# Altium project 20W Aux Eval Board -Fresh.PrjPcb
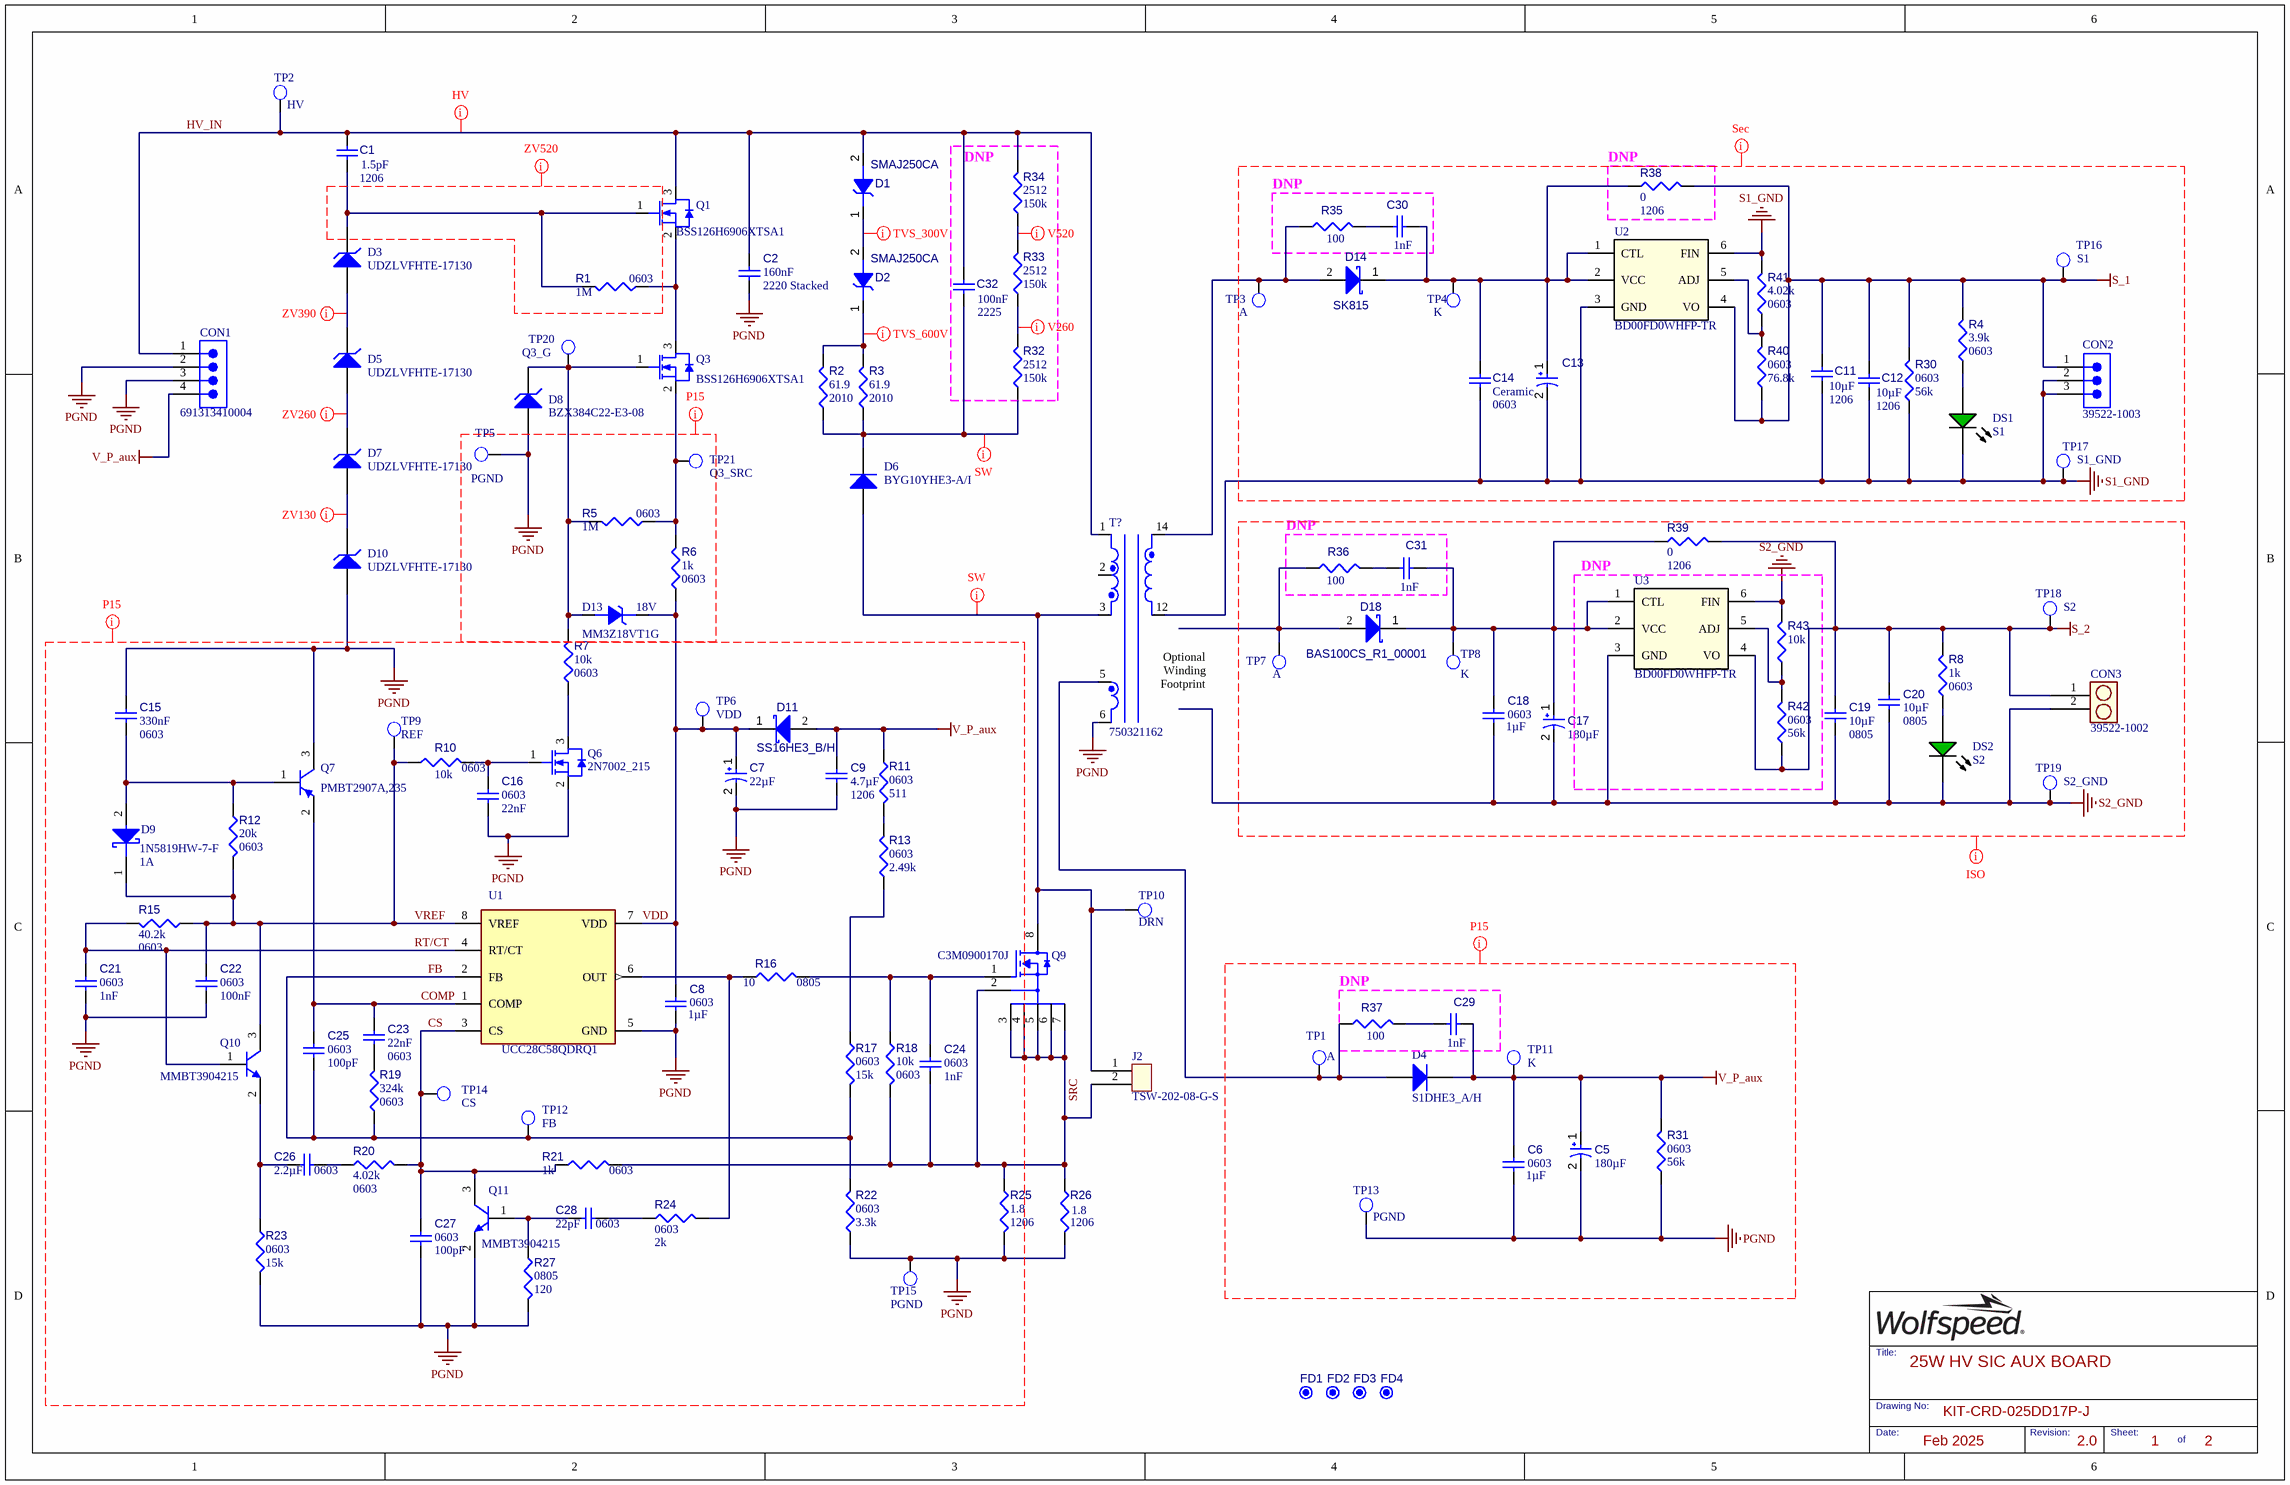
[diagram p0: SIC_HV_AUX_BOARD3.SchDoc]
Date: Feb 2025; DocumentNumber: KIT-CRD-025DD17P-J; Revision: 2.0; Title: 25W HV SIC AUX BOARD
2 sheets, 135 parts. Net scope: global (net labels, ports and power ports of the same name join across sheets).
Board file: HV_SIC_AUX_BOARD.PcbDoc
Sheets:
  SIC_HV_AUX_BOARD3.SchDoc
  Mechanicals.SchDoc

## Sheet SIC_HV_AUX_BOARD3.SchDoc: 25W HV SIC AUX BOARD
size 431 x 279 mm; SheetNumber: 1; SheetTotal: 2

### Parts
C1  value 1.5pF  Case/Package: 1206  [CAPC3316X19N]  (hidden comment: 1206Y1K01P50DAR)
C2  value 160nF  Case/Package: 2220 Stacked  [WS_C2220_B_Stacked]  (hidden comment: C2220C164KFRLCTU)
C5  value 180µF  [870235574001-Footprint-1]  (hidden comment: 870235574001)
C6  value 1µF  Case/Package: 0603  [FP-C0603C-CF-IPC_B]  (hidden comment: C1608X7R1V105K080AE)
C7  value 22µF  [875575659001-Footprint-1]  (hidden comment: 875575659001)
C8  value 1µF  Case/Package: 0603  [FP-C0603C-CF-IPC_B]  (hidden comment: C1608X7R1V105K080AE)
C9  value 4.7µF  Case/Package: 1206  [CAPC3316X19N]  (hidden comment: UMK316AB7475KL-T)
C11  value 10µF  Case/Package: 1206  [CAPC3316X19N]  (hidden comment: CL31B106KAHNFNE)
C12  value 10µF  Case/Package: 1206  [CAPC3316X19N]  (hidden comment: CL31B106KAHNFNE)
C13  EEE-FP1V221AP  [FP-FPF-MFG]  (value not drawn)
C14  Capacitor Type: Ceramic  Case/Package: 0603  [FP-C0603C-CF-IPC_B]  (hidden comment: 06035C105KAT2A)
C15  value 330nF  Case/Package: 0603  [WFP_C0603_C]  (hidden comment: CC0603KRX7R8BB334)
C16  value 22nF  Case/Package: 0603  [FP-C0603C-CF-IPC_B]  (hidden comment: CGA3E2X7R1H223K080AA)
C17  value 180µF  [WCAP-PT5H_D6.3H11]  (hidden comment: 870235373002)
C18  value 1µF  Case/Package: 0603  [FP-C0603C-CF-IPC_B]  (hidden comment: C1608X7R1V105K080AE)
C19  value 10µF  Case/Package: 0805  [CAPC2012X15N]  (hidden comment: CC0805MKX7R7BB106)
C20  value 10µF  Case/Package: 0805  [CAPC2012X15N]  (hidden comment: CC0805MKX7R7BB106)
C21  value 1nF  Case/Package: 0603  [FP-C0603C-CF-IPC_B]  (hidden comment: GRM1885C1H102GA01D)
C22  value 100nF  Case/Package: 0603  [FP-C0603C-CF-IPC_B]  (hidden comment: C0603C104K5RAC7411)
C23  value 22nF  Case/Package: 0603  [FP-C0603C-CF-IPC_B]  (hidden comment: CGA3E2X7R1H223K080AA)
C24  value 1nF  Case/Package: 0603  [FP-C0603C-CF-IPC_B]  (hidden comment: GRM1885C1H102GA01D)
C25  value 100pF  Case/Package: 0603  [FP-C0603C-CF-IPC_B]  (hidden comment: CC0603KRX7R9BB101)
C26  value 2.2µF  Case/Package: 0603  [FP-C0603C-CF-IPC_B]  (hidden comment: GMC10X7R225K16NT)
C27  value 100pF  Case/Package: 0603  [FP-C0603C-CF-IPC_B]  (hidden comment: CC0603KRX7R9BB101)
C28  value 22pF  Case/Package: 0603  [FP-C0603C-CF-IPC_B]  (hidden comment: C0603C220K5GACTU)
C29  value 1nF  [CAPC3316X19N]  (hidden comment: GRM31B5C2J102JW01L)
C30  value 1nF  [CAPC3316X19N]  (hidden comment: GRM31B5C2J102JW01L)
C31  value 1nF  [CAPC3316X19N]  (hidden comment: GRM31B5C2J102JW01L)
C32  value 100nF  Case/Package: 2225  [CAPC2225(5664)150_N]  (hidden comment: C2225C104KFRACTU)
CON1  691313410004  [691313410004]
CON2  39522-1003  [39522-1002-Footprint-1]
CON3  39522-1002  [39522-1002-Footprint-1]
D1  SMAJ250CA  [DO-214AC_SMA_B]
D2  SMAJ250CA  [DO-214AC_SMA_B]
D3  UDZLVFHTE-17130  [WS-SOD323F_B]
D4  S1DHE3_A/H  [DO-214AC_SMA_B]
D5  UDZLVFHTE-17130  [WS-SOD323F_B]
D6  BYG10YHE3-A/I  [DO-214AC_SMA_B]
D7  UDZLVFHTE-17130  [WS-SOD323F_B]
D8  BZX384C22-E3-08  [DIOD-SOD323-2-A_V]
D9  1N5819HW-7-F  Forward Current: 1A  [WS_SOD123_B]
D10  UDZLVFHTE-17130  [WS-SOD323F_B]
D11  SS16HE3_B/H  [DO-214AC_SMA_B]
D13  MM3Z18VT1G  Voltage Rating (DC): 18V  [DIOD-SOD323-2-A_V]
D14  SK815  [DO-214AB (SMC) MD]
D18  BAS100CS_R1_00001  [WS-SOD323F_B]
DS1  S1  [WL-SMCW_0603_150060xx75000]
DS2  S2  [WL-SMCW_0603_150060xx75000]
FD1  FID1X2R Two Sided  [FID1X2R Two Sided-Footprint-1]  (value not drawn)  (no BOM)
FD2  FID1X2R Two Sided  [FID1X2R Two Sided-Footprint-1]  (value not drawn)  (no BOM)
FD3  FID1X2R Two Sided  [FID1X2R Two Sided-Footprint-1]  (value not drawn)  (no BOM)
FD4  FID1X2R Two Sided  [FID1X2R Two Sided-Footprint-1]  (value not drawn)  (no BOM)
J2  TSW-202-08-G-S  [TSW-202-24-T-S-Footprint-2]
Q1  BSS126H6906XTSA1  [WFP_SOT23-3_IPC_B]
Q3  BSS126H6906XTSA1  [WFP_SOT23-3_IPC_B]
Q6  2N7002_215  [WFP_SOT23-3_IPC_B]
Q7  PMBT2907A,235  [WFP_SOT23-3_IPC_B]
Q9  C3M0900170J  [TO-263-7XL_CRW]
Q10  MMBT3904215  [NXP-SOT23_N]
Q11  MMBT3904215  [NXP-SOT23_N]
R1  value 1M  Case/Package: 0603  [FP-AC0603-IPC_B]  (hidden comment: RMCF0603FT1M00)
R2  value 61.9  Case/Package: 2010  [R2010_MD]  (hidden comment: CRCW201061R9FKEFHP)
R3  value 61.9  Case/Package: 2010  [R2010_MD]  (hidden comment: CRCW201061R9FKEFHP)
R4  value 3.9k  Case/Package: 0603  [FP-AC0603-IPC_B]  (hidden comment: RMCF0603FT3K90)
R5  value 1M  Case/Package: 0603  [FP-AC0603-IPC_B]  (hidden comment: RMCF0603FT1M00)
R6  value 1k  Case/Package: 0603  [FP-AC0603-IPC_B]  (hidden comment: RMCF0603FG1K00)
R7  value 10k  Case/Package: 0603  [FP-AC0603-IPC_B]  (hidden comment: RG1608P-103-B-T5)
R8  value 1k  Case/Package: 0603  [FP-AC0603-IPC_B]  (hidden comment: RMCF0603FG1K00)
R10  value 10k  Case/Package: 0603  [FP-AC0603-IPC_B]  (hidden comment: RG1608P-103-B-T5)
R11  value 511  Case/Package: 0603  [WFP_R0603_B]  (hidden comment: RC0603FR-07511RL)
R12  value 20k  Case/Package: 0603  [FP-AC0603-IPC_B]  (hidden comment: RMCF0603FT20K0)
R13  value 2.49k  Case/Package: 0603  [FP-AC0603-IPC_B]  (hidden comment: Copy of ERJ-3EKF2701V)
R15  value 40.2k  Case/Package: 0603  [FP-AC0603-IPC_B]  (hidden comment: AC0603FR-0740K2L)
R16  value 10  Case/Package: 0805  [RESC2012X05M]  (hidden comment: RC0805FR-1310RL)
R17  value 15k  Case/Package: 0603  [FP-AC0603-IPC_B]  (hidden comment: RT0603BRE0715KL)
R18  value 10k  Case/Package: 0603  [FP-AC0603-IPC_B]  (hidden comment: RG1608P-103-B-T5)
R19  value 324k  Case/Package: 0603  [FP-AC0603-IPC_B]  (hidden comment: AC0603FR-07324KL)
R20  value 4.02k  Case/Package: 0603  [FP-AC0603-IPC_B]  (hidden comment: RMCF0603FT4K02)
R21  value 1k  Case/Package: 0603  [FP-AC0603-IPC_B]  (hidden comment: RMCF0603FG1K00)
R22  value 3.3k  Case/Package: 0603  [FP-AC0603-IPC_B]  (hidden comment: RMCF0603FT3K30)
R23  value 15k  Case/Package: 0603  [FP-AC0603-IPC_B]  (hidden comment: RT0603BRE0715KL)
R24  value 2k  Case/Package: 0603  [FP-AC0603-IPC_B]  (hidden comment: ERJ-3EKF2001V)
R25  value 1.8  Case/Package: 1206  [RESC3015X06N]  (hidden comment: CRCW12061R80FKEAHP)
R26  value 1.8  Case/Package: 1206  [RESC3015X06N]  (hidden comment: CRCW12061R80FKEAHP)
R27  value 120  Case/Package: 0805  [FP-CRGP0805-IPC_B]  (hidden comment: CRGP0805F120R)
R30  value 56k  Case/Package: 0603  [FP-AC0603-IPC_B]  (hidden comment: 56k 0603)
R31  value 56k  Case/Package: 0603  [FP-AC0603-IPC_B]  (hidden comment: 56k 0603)
R32  value 150k  Case/Package: 2512  [RESC6332X07N]  (hidden comment: CRCW2512150KFKEG)
R33  value 150k  Case/Package: 2512  [RESC6332X07N]  (hidden comment: CRCW2512150KFKEG)
R34  value 150k  Case/Package: 2512  [RESC6332X07N]  (hidden comment: CRCW2512150KFKEG)
R35  value 100  [RESC3015X06N]  (hidden comment: CRCW1206100RFKEA)
R36  value 100  [RESC3015X06N]  (hidden comment: CRCW1206100RFKEA)
R37  value 100  [RESC3015X06N]  (hidden comment: CRCW1206100RFKEA)
R38  value 0  Case/Package: 1206  [RESC3015X06N]  (hidden comment: RC1206JR-100RL)
R39  value 0  Case/Package: 1206  [RESC3015X06N]  (hidden comment: RC1206JR-100RL)
R40  value 76.8k  Case/Package: 0603  [FP-AC0603-IPC_B]  (hidden comment: RC0603FR-0776K8L)
R41  value 4.02k  Case/Package: 0603  [FP-AC0603-IPC_B]  (hidden comment: RMCF0603FT4K02)
R42  value 56k  Case/Package: 0603  [FP-AC0603-IPC_B]  (hidden comment: 56k 0603)
R43  value 10k  [FP-AC0603-IPC_B]  (hidden comment: Resistor 10k +/-1% 0603 100 mW)
T?  750321162  [750345357-Footprint-1]
TP1  A  [TEST_POINT_SM_REC]
TP2  HV  [TEST_POINT_SM_REC]
TP3  A  [TEST_POINT_SM_REC]
TP4  K  [TEST_POINT_SM_REC]
TP5  PGND  [5012-Footprint-1]
TP6  VDD  [TEST_POINT_SM_REC]
TP7  A  [TEST_POINT_SM_REC]
TP8  K  [TEST_POINT_SM_REC]
TP9  REF  [TEST_POINT_SM_REC]
TP10  DRN  [TEST_POINT_SM_REC]
TP11  K  [TEST_POINT_SM_REC]
TP12  FB  [TEST_POINT_SM_REC]
TP13  PGND  [5012-Footprint-1]
TP14  CS  [TEST_POINT_SM_REC]
TP15  PGND  [5012-Footprint-1]
TP16  S1  [5012-Footprint-1]
TP17  S1_GND  [5012-Footprint-1]
TP18  S2  [5012-Footprint-1]
TP19  S2_GND  [5012-Footprint-1]
TP20  Q3_G  [TEST_POINT_SM_REC]
TP21  Q3_SRC  [TEST_POINT_SM_REC]
U1  UCC28C58QDRQ1  [WFP_SOIC127P6-8_IPC-B]
U2  BD00FD0WHFP-TR  [BD00FD0WHFP-TR-Footprint-1]
U3  BD00FD0WHFP-TR  [BD00FD0WHFP-TR-Footprint-1]

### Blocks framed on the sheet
DNP: C32 R32-R34
DNP: C30 R35
DNP: R38
DNP: C31 R36
DNP: R42 R43 U3
DNP: C29 R37

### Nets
PGND: C2.2 C5.2 C6.2 C7.2 C8.2 C9.2 C15.2 C16.1 C21.1 C22.1 C27.1 CON1.2 CON1.3 D8.2(A) D10.2(A) Q6.2(S) Q7.3(C) Q11.2(E) R22.1 R23.2 R25.2 R26.2 R27.2 R31.1 T?.6(Pri2-) TP5.1(TP) TP13.1(TP) TP15.1(TP) U1.5(GND)
S1_GND: C11.2 C12.2 C13.2 C14.2 CON2.2 CON2.3 DS1.1(K) R30.1 R41.2 T?.12(Sec1-) TP17.1(TP) U2.3(GND) U2.6(FIN)
S2_GND: C17.2 C18.2 C19.1 C20.1 CON3.2 DS2.1(K) R43.2 TP19.1(TP) U3.3(GND) U3.6(FIN)
S_1: C11.1 C12.1 CON2.1 R4.2 R30.2 R38.2 R40.1 TP16.1(TP) U2.4(VO)
S_2: C19.2 C20.2 CON3.1 R8.2 R39.2 R42.1 TP18.1(TP) U3.4(VO)
V_P_aux: C5.1 C6.1 C9.1 C29.1 CON1.4 D4.1(K) D11.2(A) R11.1 R31.2 TP11.1(TP)
COMP: C23.2 C25.2 Q7.2(E) U1.1(COMP)
CS: C27.2 Q11.3(C) R20.2 R21.1 TP14.1(TP) U1.3(CS)
FB: C25.1 R17.2 R19.1 R22.2 TP12.1(TP) U1.2(FB)
HV_IN: C1.1 C2.1 C32.1 CON1.1 D1.2(A) Q1.3(D) R34.1 T?.1(Pri1+) TP2.1(TP)
RT/CT: C21.2 Q10.1(B) R15.2 U1.4(RT/CT)
SRC: C24.1 J2.2 Q9.2(Driver_Source) Q9.3(Power_Source) Q9.4(Power_Source) Q9.5(Power_Source) Q9.6(Power_Source) Q9.7(Power_Source) R18.2 R21.2 R25.1 R26.1
VDD: C7.1 C8.1 D11.1(K) D13.2(CATHODE) R6.1 TP6.1(TP) U1.7(VDD)
VREF: C22.2 D9.1(C) Q10.3(C) R10.1 R12.2 R15.1 TP9.1(TP) U1.8(VREF)
NetC1_2: C1.2 D3.1(K) Q1.1(G) R1.2
NetC13_1: C13.1 C14.1 C30.1 D14.1(K) R38.1 TP4.1(TP) U2.1(CTL) U2.2(VCC)
NetC15_1: C15.1 D9.2(A) Q7.1(B) R12.1
NetC16_2: C16.2 Q6.1(G) R10.2
NetC17_1: C17.1 C18.1 C31.1 D18.1(K) R39.1 TP8.1(TP) U3.1(CTL) U3.2(VCC)
NetC23_1: C23.1 R19.2
NetC24_2: C24.2 Q9.1(Gate) R16.2 R18.1
NetC26_1: C26.1 Q10.2(E) R23.1
NetC26_2: C26.2 R20.1
NetC28_1: C28.1 R24.1
NetC28_2: C28.2 Q11.1(B) R27.1
NetC29_2: C29.2 R37.2
NetC30_2: C30.2 R35.2
NetC31_2: C31.2 R36.2
NetC32_2: C32.2 D6.1(K) R2.1 R3.1 R32.2
NetD1_1: D1.1(A) D2.2(A)
NetD2_1: D2.1(A) R2.2 R3.2
NetD3_2: D3.2(A) D5.1(K)
NetD4_2: D4.2(A) R37.1 T?.5(Pri2+) TP1.1(TP)
NetD5_2: D5.2(A) D7.1(K)
NetD6_2: D6.2(A) J2.1 Q9.8(Drain) T?.3(Pri1-) TP10.1(TP)
NetD7_2: D7.2(A) D10.1(K)
NetD8_1: D8.1(K) D13.1(ANODE) Q3.1(G) R5.2 R7.2 TP20.1(TP)
NetD14_2: D14.2(A) R35.1 T?.14(Sec1+) TP3.1(TP)
NetD18_2: D18.2(A) R36.1 TP7.1(TP)
NetDS1_2: DS1.2(A) R4.1
NetDS2_2: DS2.2(A) R8.1
NetQ1_2: Q1.2(S) Q3.3(D) R1.1
NetQ3_2: Q3.2(S) R5.1 R6.2 TP21.1(TP)
NetQ6_3: Q6.3(D) R7.1
NetR11_2: R11.2 R13.2
NetR13_1: R13.1 R17.1
NetR16_1: R16.1 R24.2 U1.6(OUT)
NetR32_1: R32.1 R33.2
NetR33_1: R33.1 R34.2
NetR40_2: R40.2 R41.1 U2.5(ADJ)
NetR42_2: R42.2 R43.1 U3.5(ADJ)

Not connected (* = marked no-connect by the designer): T? 2(Pri1+)

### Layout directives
net class Sec: S1_GND, S_1
net class ISO: S2_GND, S_2
net class P15: COMP, CS, FB, PGND, RT/CT, V_P_aux, VDD, VREF
net class HV: HV_IN
net class ZV130: NetD7_2
net class ZV260: NetD5_2
net class ZV390: NetD3_2
net class SW: NetC32_2, NetD6_2
net class V260: NetR32_1
net class ZV520: (no net found under the mark)
net class V520: NetR33_1
net class TVS_300V: NetD1_1
net class TVS_600V: NetD2_1

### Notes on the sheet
- (near T?) Optional Winding Footprint

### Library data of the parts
C1 = CMP-001-00194-6: MLCC, 1206, Y5V, 1uf, .10%, 0.50Vdc, Palliadum Silver; Capacitor Type: Ceramic; Temperature Coefficient: COG/NPO; Tolerance: 33%; Voltage Rating: 1kV
C2 = CMP-001-00220-1: 0.16 µF ±10% 1500V (1.5kV) Ceramic Capacitor X7R 2220
C5 = CMP-001-00223-1: WCAP-PT5H Aluminum Polymer Capacitors, 180uF, 16VDC, +/-20%; Capacitor Type: Electrolytic; Tolerance: 20%; Voltage Rating: 16V
C6 C8 C18 = CMP-001-00097-20: Ceramic Capacitor, Multilayer, Ceramic, 35V, 10% +Tol, 10% -Tol, X7R, 15% TC, 1uF, Surface Mount, 0603
C7 = CMP-001-00222-1: WCAP-ASLL Aluminum Hybrid Electrolytic Capacitor, 22uF, 35VDC, +/-20%; Tolerance: 20%; Voltage Rating: 35V
C9 = CMP-001-00161-7: Ceramic Capacitor, Multilayer, Ceramic, 4.7 µF ±10% 50V Ceramic Capacitor X7R 1206
C11 C12 = CMP-001-00158-8: Cap Ceramic 10uF 25V X7R 10% SMD 1206 125°C Embossed T/R
C13 = CMP-001-00219-2: Aluminum Electrolytic Capacitor, Polarized, Aluminum (wet), 35V, 20% +Tol, 20% -Tol, 220uF, Surface Mount, 3333; Capacitor Type: Aluminium; Value: 220µF
C14 = CMP-001-00122-18: Ceramic Capacitor, Multilayer, Ceramic, 50V, 10% +Tol, 10% -Tol, X7R, 15% TC, 1uF, Surface Mount, 0603; Value: 1µF
C15 = CMP-001-00201-6: Ceramic Capacitor, Multilayer, Ceramic, 25V, 10% +Tol, 10% -Tol, X7R, 15% TC, 0.33uF, Surface Mount, 0603
C16 C23 = CMP-001-00120-19: Ceramic Capacitor, Multilayer, Ceramic, 50V, 10% +Tol, 10% -Tol, X7R, 15% TC, 0.022uF, Surface Mount, 0603
C17 = CMP-001-00221-1: CAP ALUM POLY 180UF 20% 16V TH; Capacitor Type: Aluminium
C19 C20 = CMP-001-00199-5: Ceramic Capacitor, Multilayer, Ceramic, 16V, 20% +Tol, 20% -Tol, X7R, 15% TC, 10uF, Surface Mount, 0805
C21 C24 = CMP-001-00098-21: Ceramic Capacitor, Multilayer, Ceramic, 50V, 2% +Tol, 2% -Tol, C0G, -/+30ppm/Cel TC, 0.001uF, Surface Mount, 0603
C22 = CMP-001-00086-20: Ceramic Capacitor, Multilayer, Ceramic, 50V, 10% +Tol, 10% -Tol, X7R, 15% TC, 0.1uF, Surface Mount, 0603
C25 C27 = CMP-001-00096-18: Ceramic Capacitor, Multilayer, Ceramic, 50V, 10% +Tol, 10% -Tol, X7R, 15% TC, 0.0001uF, Surface Mount, 0603
C26 = CMP-001-00123-18: Ceramic Capacitor, Multilayer, Ceramic, 16V, 10% +Tol, 10% -Tol, X7R, 15% TC, 2.2uF, Surface Mount, 0603
C28 = CMP-001-00112-18: Ceramic Capacitor, Multilayer, Ceramic, 50V, 1% +Tol, 1% -Tol, C0G, 30ppm/Cel TC, 0.000022uF, Surface Mount, 0603
C29-C31 = CMP-001-00217-1: Ceramic Capacitor, Multilayer, Ceramic, 630V, 5% +Tol, 5% -Tol, C0G, 30ppm/Cel TC, 0.001uF, Surface Mount, 1206; Temperature Coefficient: COG
C32 = CMP-001-00008-7: Cap Ceramic 0.1uF 1500V X7R 10% SMD 2225 125°C Embossed Plastic T/R; Voltage Rating: 1.5kV
CON1 = CMP-002-00276-1: Strip Terminal Block, 20A, 1 Row(s), 1 Deck(s); Connector Type: Shrouded Header; Gender: Male; Rated Voltage: 300V
CON2 = CMP-002-00195-6: Conn Shrouded Header (4 Sides) HDR 3 POS 5mm Solder RA Thru-Hole Eurostyle™; Gender: Male; Connector Type: Terminal Block
CON3 = CMP-002-00120-6: Conn Shrouded Header (4 Sides) HDR 2 POS 5mm Solder RA Thru-Hole Eurostyle™; Connector Type: Terminal Block; Gender: Male
D1 D2 = CMP-004-00090-2: TVS DIODE 250VWM 405VC DO214AC405V Clamp 1A Ipp Tvs Diode Surface Mount DO-214AC
D3 D5 D7 D10 = CMP-004-00084-2: Zener Diode, 130V, 0.2W, Sod-323Fl Rohs Compliant: Yes; Zener Voltage: 130
D4 = CMP-004-00089-3: Rectifier Diode, 1 Phase, 1 Element, 1A, 400V V(RRM), Silicon, DO-214AC; Forward Voltage: 1.1V; Max Surge Current: 40A; Peak Inverse Voltage: 200V
D6 = CMP-004-00085-3: Standard Avalanche Rectifier 1600V 1.5A Automotive 2-Pin DO-214AC T/R; Forward Voltage: 1.15V; Max Surge Current: 30A; Peak Inverse Voltage: 1.6kV
D8 = CMP-004-00086-2: Zener Diode, 22V V(Z), 5%, 0.2W, Silicon, Unidirectional
D9 = CMP-004-00065-4: DIODE SCHOTTKY 40V 1A SOD123; Forward Voltage: 450mV
D11 = CMP-00035-3: Rectifier Diode, Schottky, 1 Phase, 1 Element, 1A, 60V V(RRM), Silicon, DO-214AC; Forward Voltage: 750mV; Max Surge Current: 40A
D13 = CMP-00028-3: Vz=18V 16.8V~19.1V Izt=5mA; Material: Plastic; Tolerance: 6%; Max Power Dissipation: 300mW; Max Reverse Current: 50nA; Power Rating: 200mW; Impedance: 45R; Zener Current: 10mA; Test Current: 5mA; Forward Voltage: 900mV
D14 = CMP-00045-2: Rectifier Diode Schottky 150V 8A 2-Pin SMC T/R; Forward Voltage: 870mV
D18 = CMP-00037-1: OEMs, CMs ONLY (NO BROKERS); Forward Voltage: 850mV; Max Surge Current: 5.5A; Peak Inverse Voltage: 100V
DS1 DS2 = CMP-007-00045-2: Single Color LED, Bright Green, Water Clear, 1.1mm; Forward Voltage: 2V; Max Power Dissipation: 72mW
FD1-FD4 = CMP-00028-00054-3: Fiducial - Round 1x2mm
J2 = CMP-002-00256-2: Board Connector, 2 Contact(s), 1 Row(s), Male, Straight, 0.2 inch Pitch, Solder Terminal, Black Insulator, Receptacle
Q1 Q3 = CMP-013-00102-1: Trans MOSFET N-CH 600V 0.021A Automotive 3-Pin SOT-23 T/R; Vgs (Max): 20V; Transistor Type: NMOS; Power: 500mW
Q6 = CMP-013-00011-7: N-channel Trench MOSFET, 60 V, 300 mA, -65 to 150 degC, 3-Pin SOT-23 (TO-236AB), RoHS, Tape and Reel; Manufacturer: NXP Semiconductors; Input Capacitance: 50pF; Rds On Max: 5Ohm; Vds Max: 60V; Package Version: Feb-16; Nominal Vgs: 2V; Elements: 1; Power: 830mW
Q7 = CMP-013-00100-1: Small Signal Bipolar Transistor, 0.6A I(C), 60V V(BR)CEO, 1-Element, PNP, Silicon, TO-236AB; Power: 250mW
Q9 = CMP-013-00114-3: 1700V 900 M SIC MOSFET; Transistor Type: N-Channel Enhancement Mode MOSFET
Q10 Q11 = CMP-013-00098-1: Single Bipolar Transistor, NPN, 40 V, 200 mA, 250 mW, TO-236AB (SOT-23), 3 Pins, Surface Mount; Power: 250mW
R1 R5 = CMP-009-00047-7: Fixed Resistor, Metal Glaze/thick Film, 0.1W, 1000000ohm, 75V, 1% +/-Tol, 100ppm/Cel, Surface Mount, 0603; Power: 100mW
R2 R3 = CMP-009-00313-1: Fixed Resistor, Metal Glaze/thick Film, 1W, 61.9ohm, 400V, 1% +/-Tol, 100ppm/Cel, Surface Mount, 2010
R4 = CMP-009-00033-7: Fixed Resistor, Metal Glaze/thick Film, 0.1W, 3900ohm, 75V, 1% +/-Tol, 100ppm/Cel, Surface Mount, 0603; Power: 100mW
R6 R8 R21 = CMP-009-00009-6: Fixed Resistor, Metal Glaze/thick Film, 0.1W, 1000ohm, 75V, 1% +/-Tol, 100ppm/Cel, Surface Mount, 0603; Power: 100mW
R7 R10 R18 = CMP-009-00206-6: Res SMD 10K Ohm 0.1% 1/10W 0603; Power: 100mW; Voltage Rating: 75V
R11 = CMP-009-00377-1: Fixed Resistor, Metal Glaze/thick Film, 0.1W, 511ohm, 75V, 1% +/-Tol, 100ppm/Cel, Surface Mount, 0603; Power: 100mW
R12 = CMP-009-00039-7: Fixed Resistor, Metal Glaze/thick Film, 0.1W, 20000ohm, 75V, 1% +/-Tol, 100ppm/Cel, Surface Mount, 0603; Power: 100mW
R13 = CMP-009-00227-4: Fixed Resistor, Metal Glaze/thick Film, 0.1W, 2490ohm, 75V, 1% +/-Tol, 100ppm/Cel, Surface Mount, 0603; Power: 100mW
R15 = CMP-009-00311-1: Fixed Resistor, Metal Glaze/thick Film, 0.1W, 40200ohm, 75V, 1% +/-Tol, 100ppm/Cel, Surface Mount, 0603; Power: 100mW
R16 = CMP-009-00217-1: RC Series 0805 0.125 W 10 Ohm ±1% ±100 ppm/°C SMT Thick Film Chip Resistor; Voltage Rating: 150V; MFG: Yageo; Power: 125mW
R17 R23 = CMP-009-00107-6: Fixed Resistor, Metal Glaze/thick Film, 0.1W, 15000ohm, 75V, 0.1% +/-Tol, 50ppm/Cel, Surface Mount, 0603; Power: 100mW
R19 = CMP-009-00312-1: Fixed Resistor, Metal Glaze/thick Film, 0.1W, 324000ohm, 75V, 1% +/-Tol, 100ppm/Cel, Surface Mount, 0603; Power: 100mW
R20 R41 = CMP-009-00034-7: Fixed Resistor, Metal Glaze/thick Film, 0.1W, 4020ohm, 75V, 1% +/-Tol, 100ppm/Cel, Surface Mount, 0603; Power: 100mW
R22 = CMP-009-00032-7: Fixed Resistor, Metal Glaze/thick Film, 0.1W, 3300ohm, 75V, 1% +/-Tol, 100ppm/Cel, Surface Mount, 0603; Power: 100mW
R24 = CMP-009-00027-8: Fixed Resistor, Metal Glaze/thick Film, 0.1W, 2000ohm, 75V, 1% +/-Tol, 100ppm/Cel, Surface Mount, 0603; Power: 100mW
R25 R26 = CMP-009-00314-4: Fixed Resistor, Metal Glaze/thick Film, 0.75W, 1.8ohm, 200V, 1% +/-Tol, 100ppm/Cel, Surface Mount, 1206; Power: 750mW
R27 = CMP-009-00216-1: Res Pulse Withstand Thick Film 0805 120 Ohm 1% 1/3W ±100ppm/°C Molded Paper T/R; MFG: TE Connectivity Passive Product; Power: 330mW
R30 R31 R42 = CMP-009-00232-4: Fixed Resistor, Metal Glaze/thick Film, 0.1W, 56000ohm, 75V, 1% +/-Tol, 100ppm/Cel, Surface Mount, 0603; Power: 100mW
R32-R34 = CMP-009-00080-4: Fixed Resistor, Metal Glaze/thick Film, 1W, 150000ohm, 500V, 1% +/-Tol, 100ppm/Cel, Surface Mount, 2512
R35-R37 = CMP-009-00345-1: Fixed Resistor, Metal Glaze/thick Film, 0.25W, 100ohm, 200V, 1% +/-Tol, 100ppm/Cel, Surface Mount, 1206; Power: 250mW
R38 R39 = CMP-009-00090-7: Fixed Resistor, Metal Glaze/thick Film, 0.25W, 0ohm, 200V, 5% +/-Tol, 100ppm/Cel, Surface Mount, 1206; Power: 250mW
R40 = CMP-009-00347-1: Fixed Resistor, Metal Glaze/thick Film, 0.1W, 76800ohm, 75V, 1% +/-Tol, 100ppm/Cel, Surface Mount, 0603; Power: 100mW
R43 = CMP-009-00017-6: Chip Resistor, 10 KOhm, +/- 1%, 01 W, -55 to 155 degC, 0603 (1608 Metric); Voltage Rating: 50V; Power: 100mW
T? = CMP-012-00017-1: TRANSFORMERS 800uH
TP1-TP4 TP6-TP12 TP14 TP20 TP21 = CMP-017-000000-3: HARWIN - S1751-46R - PCB Test Point, S1751 Series, Surface Mount, Brass, Tin Plated Contacts
TP5 TP13 TP15-TP19 = CMP-017-000005-3: Test Point MultiPurpose THM .445 L .125 OD Heat Resistant Nylon 46 White
U1 = CMP-00024-00042-4: Automotive, 30-V, low-power current-mode PWM controller, 16-V/12.5-V UVLO for SiC, 100% duty cycle 8-SOIC -40 to 150
U2 U3 = CMP-019-00117-2: LDO Regulator Pos 1.5V to 16V 2A 6-Pin(5+Tab) HRP Tape; ADJ Range (min V-max V): 1.5V-18V; Max Supply Voltage: 32V; Type (Fixed/ADJ): Adjustable

## Sheet Mechanicals.SchDoc: -
size 431 x 279 mm; Date: -; Revision: -; SheetNumber: 2; SheetTotal: 2
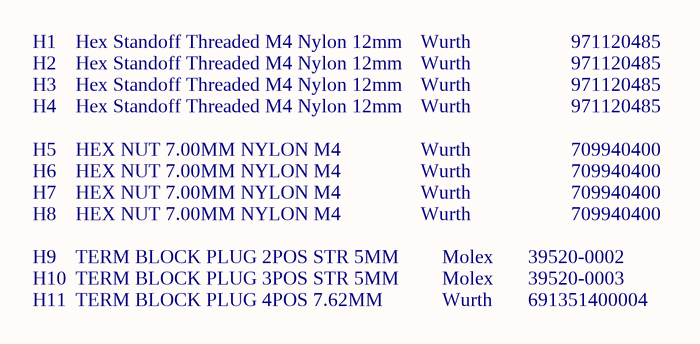
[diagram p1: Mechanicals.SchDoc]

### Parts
H1  971120485  (value not drawn)
H2  971120485  (value not drawn)
H3  971120485  (value not drawn)
H4  971120485  (value not drawn)
H5  709940400  (value not drawn)
H6  709940400  (value not drawn)
H7  709940400  (value not drawn)
H8  709940400  (value not drawn)
H9  39520-0002  [39520-0002-Footprint-1]  (value not drawn)  (mechanical)
H10  39520-0003  [39520-0003-Footprint-1]  (value not drawn)  (mechanical)
H11  691351400004  [691351400004]  (value not drawn)

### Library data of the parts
H1-H4 = CMP-00028-00074-1: WA-SPaIE Plastic Spacer Thread int./ext.
H5-H8 = CMP-00028-00075-1: WA-SNTE Plastic Hexagon Nut
H9 = CMP-00028-00013-2: Conn Eurostyle Block F 2 POS 5mm Screw RA Cable Mount 18A/Contact Eurostyle™
H10 = CMP-00028-00071-1: 3 Position Terminal Block Plug, Female Sockets 0.197" (5.00mm) 180° Free Hanging (In-Line); Current Rating: 15A; Fastening Method: SCREW; Number of Decks: 1; Number of Ways: 3; Voltage Rating: 300V; Wire/Cable Gauge: 12AWG
H11 = CMP-00028-00078-1: Barrier Strip Terminal Block, 20A, 3mm2, 1 Row(s), 1 Deck(s); Current Rating: 12A; Fastening Method: SCREW; Number of Decks: 1; Number of Ways: 4; Voltage Rating: 400V; Wire/Cable Gauge: 12AWG

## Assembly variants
Prod. Variant of KIT-CRD-025DD17P-J: not fitted C29 C30 C31 C32 R32 R33 R34 R35 R36 R37 R38 R42 R43 U3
